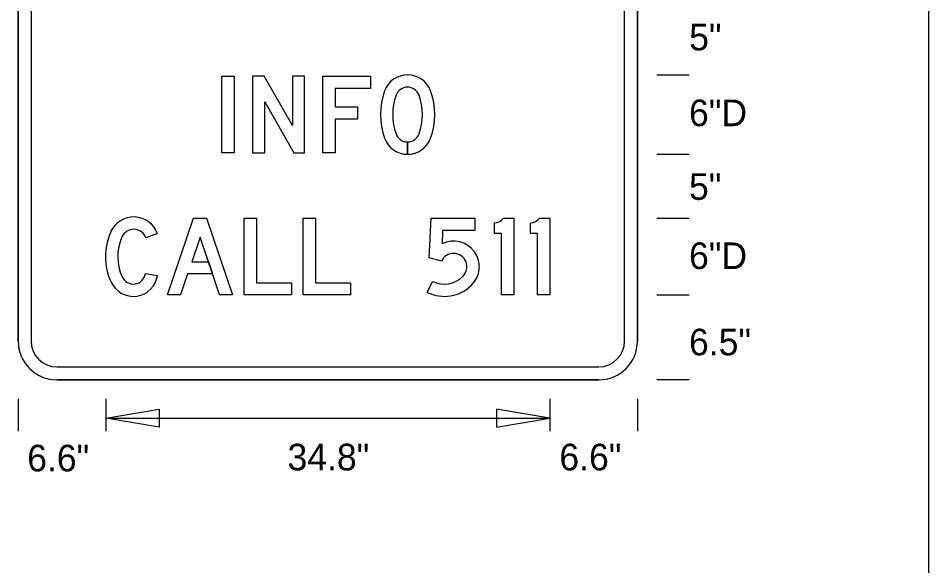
# Model space of a CAD drawing. Extents: x 0 to 770, y 0 to 495.
# Drawn here: x 265.1 to 385, y 345.2 to 417.2 of the extents above; entities that cross this region are included whole.
import ezdxf

# ---------------------------------------------------------------- set-up
doc = ezdxf.new("R2010")
doc.units = 0
for name, color, linetype in [('Default', 7, 'Continuous'), ('Dimension', 7, 'Continuous'), ('GSBWFill', 7, 'Continuous'), ('GSColorFill', 7, 'Continuous'), ('GSDims', 7, 'Continuous'), ('GSOutline', 7, 'Continuous'), ('SheetLines_dp', 7, 'Continuous'), ('TextStructures', 7, 'Continuous')]:
    doc.layers.add(name, color=color, linetype=linetype)

msp = doc.modelspace()

# ---------------------------------------------------------------- linework, layer by layer
at = {"layer": 'Default'}
for p, q in [((265.11, 466.49), (265.11, 374.77)), ((265.11, 374.77), (265.11, 466.49)), ((266.8, 466.49), (266.8, 374.77)), ((344.94, 374.77), (344.94, 466.49)), ((346.64, 374.77), (346.64, 466.49)), ((346.64, 466.49), (346.64, 374.77)), ((270.2, 371.37), (341.54, 371.37)), ((270.2, 369.67), (341.54, 369.67)), ((341.54, 369.67), (270.2, 369.67))]:
    msp.add_line(p, q, dxfattribs=at)
for centre, radius, start, end in [((270.2, 374.77), 5.1, 180, 270), ((270.2, 374.77), 5.1, 180, 270), ((270.2, 374.77), 3.4, 180, 270), ((341.54, 374.77), 5.1, 270, 0), ((341.54, 374.77), 5.1, 270, 0), ((341.54, 374.77), 3.4, 270, 0)]:
    msp.add_arc(centre, radius, start, end, dxfattribs=at)
at = {"layer": 'Dimension'}
for points in [[(276.66, 364.62), (283.67, 365.81), (283.67, 363.43)], [(335.09, 364.62), (328.07, 365.81), (328.07, 363.43)]]:
    msp.add_lwpolyline(points, close=True, dxfattribs=at)
at = {"layer": 'GSBWFill'}
for p, q in [((316.37, 400.95), (316.37, 399.34)), ((316.38, 399.34), (316.38, 400.95)), ((283.45, 388.9), (281.93, 388.35)), ((281.86, 383.64), (283.45, 383.4)), ((318.95, 381.17), (319.66, 382.62)), ((319.66, 382.62), (319.66, 382.62))]:
    msp.add_line(p, q, dxfattribs=at)
for points in [[(291.92, 409.6), (293.53, 409.6), (293.53, 399.51), (291.92, 399.51)], [(302.81, 399.51), (302.81, 409.6), (301.2, 409.6), (301.2, 403.12), (297.49, 409.6), (295.95, 409.6), (295.95, 399.51), (297.57, 399.51), (297.57, 406.22), (301.4, 399.51)], [(311.48, 409.6), (311.48, 407.98), (306.84, 407.98), (306.84, 405.56), (309.78, 405.56), (309.78, 403.95), (306.84, 403.95), (306.84, 399.51), (305.23, 399.51), (305.23, 409.6)], [(284.76, 380.83), (288.19, 390.91), (289.91, 390.91), (293.33, 380.83), (291.63, 380.83), (289.05, 388.42), (287.96, 385.21), (290.14, 385.21), (290.69, 383.6), (287.41, 383.6), (286.47, 380.83)], [(296.46, 382.44), (301.1, 382.44), (301.1, 380.83), (294.85, 380.83), (294.85, 390.91), (296.46, 390.91)], [(304.23, 382.44), (308.87, 382.44), (308.87, 380.83), (302.61, 380.83), (302.61, 390.91), (304.23, 390.91)]]:
    msp.add_lwpolyline(points, close=True, dxfattribs=at)
for points in [[(320.82, 385.27), (319.2, 385.72), (319.46, 390.91), (325.25, 390.91), (325.25, 389.3), (320.99, 389.3), (320.91, 387.55)], [(328.99, 390.91), (330.35, 390.91), (330.35, 380.83), (328.73, 380.83), (328.73, 388.9), (327.83, 388.9), (327.83, 390.3)], [(333.73, 390.91), (335.09, 390.91), (335.09, 380.83), (333.47, 380.83), (333.47, 388.9), (332.57, 388.9), (332.57, 390.3)]]:
    msp.add_lwpolyline(points, dxfattribs=at)
for centre, radius, start, end in [((280.32, 387.76), 3.33, 20.0236, 155.9453), ((327.55, 392.22), 1.94, 278.1148, 317.6823), ((332.29, 392.22), 1.94, 278.1148, 317.6823), ((284.56, 385.87), 7.97, 155.9453, 204.848), ((284.56, 385.87), 6.35, 155.9453, 204.848), ((280.32, 387.76), 1.71, 20.0236, 155.9453), ((322.43, 384.53), 3.38, 314.4153, 116.7914), ((322.43, 384.53), 1.76, 314.4153, 155.5257), ((280.26, 383.88), 3.23, 204.848, 351.506), ((280.26, 383.88), 1.61, 204.848, 351.506), ((321.2, 385.79), 3.53, 244.1304, 314.4153), ((321.2, 385.79), 5.14, 244.1304, 314.4153)]:
    msp.add_arc(centre, radius, start, end, dxfattribs=at)
for centre, major_axis, start_param, end_param in [((316.37, 406.55), (0, 3.23), 5.063177, 7.503193), ((321.82, 404.56), (0, 9.02), 1.220008, 1.921585), ((316.37, 406.55), (0, 1.61), 5.063177, 7.503193), ((310.93, 404.56), (0, 9.02), 4.361601, 5.063177), ((321.82, 404.56), (0, 7.41), 1.220008, 1.921585), ((310.93, 404.56), (0, 7.41), 4.361601, 5.063177), ((316.37, 402.56), (0, 1.61), 1.921585, 3.141593), ((316.37, 402.56), (0, 1.61), 3.141905, 4.361601), ((316.37, 402.56), (0, 3.23), 1.921585, 3.141593), ((316.37, 402.56), (0, 3.23), 3.141749, 4.361601)]:
    msp.add_ellipse(centre, major_axis=major_axis, ratio=0.999993, start_param=start_param, end_param=end_param, dxfattribs=at)
at = {"layer": 'GSColorFill'}
for p, q in [((316.37, 400.95), (316.37, 399.34)), ((316.38, 399.34), (316.38, 400.95)), ((283.45, 388.9), (281.93, 388.35)), ((281.86, 383.64), (283.45, 383.4)), ((318.95, 381.17), (319.66, 382.62)), ((319.66, 382.62), (319.66, 382.62))]:
    msp.add_line(p, q, dxfattribs=at)
for points in [[(291.92, 409.6), (293.53, 409.6), (293.53, 399.51), (291.92, 399.51)], [(302.81, 399.51), (302.81, 409.6), (301.2, 409.6), (301.2, 403.12), (297.49, 409.6), (295.95, 409.6), (295.95, 399.51), (297.57, 399.51), (297.57, 406.22), (301.4, 399.51)], [(311.48, 409.6), (311.48, 407.98), (306.84, 407.98), (306.84, 405.56), (309.78, 405.56), (309.78, 403.95), (306.84, 403.95), (306.84, 399.51), (305.23, 399.51), (305.23, 409.6)], [(284.76, 380.83), (288.19, 390.91), (289.91, 390.91), (293.33, 380.83), (291.63, 380.83), (289.05, 388.42), (287.96, 385.21), (290.14, 385.21), (290.69, 383.6), (287.41, 383.6), (286.47, 380.83)], [(296.46, 382.44), (301.1, 382.44), (301.1, 380.83), (294.85, 380.83), (294.85, 390.91), (296.46, 390.91)], [(304.23, 382.44), (308.87, 382.44), (308.87, 380.83), (302.61, 380.83), (302.61, 390.91), (304.23, 390.91)]]:
    msp.add_lwpolyline(points, close=True, dxfattribs=at)
for points in [[(320.82, 385.27), (319.2, 385.72), (319.46, 390.91), (325.25, 390.91), (325.25, 389.3), (320.99, 389.3), (320.91, 387.55)], [(328.99, 390.91), (330.35, 390.91), (330.35, 380.83), (328.73, 380.83), (328.73, 388.9), (327.83, 388.9), (327.83, 390.3)], [(333.73, 390.91), (335.09, 390.91), (335.09, 380.83), (333.47, 380.83), (333.47, 388.9), (332.57, 388.9), (332.57, 390.3)]]:
    msp.add_lwpolyline(points, dxfattribs=at)
for centre, radius, start, end in [((280.32, 387.76), 3.33, 20.0236, 155.9453), ((327.55, 392.22), 1.94, 278.1148, 317.6823), ((332.29, 392.22), 1.94, 278.1148, 317.6823), ((284.56, 385.87), 7.97, 155.9453, 204.848), ((284.56, 385.87), 6.35, 155.9453, 204.848), ((280.32, 387.76), 1.71, 20.0236, 155.9453), ((322.43, 384.53), 3.38, 314.4153, 116.7914), ((322.43, 384.53), 1.76, 314.4153, 155.5257), ((280.26, 383.88), 3.23, 204.848, 351.506), ((280.26, 383.88), 1.61, 204.848, 351.506), ((321.2, 385.79), 3.53, 244.1304, 314.4153), ((321.2, 385.79), 5.14, 244.1304, 314.4153)]:
    msp.add_arc(centre, radius, start, end, dxfattribs=at)
for centre, major_axis, start_param, end_param in [((316.37, 406.55), (0, 3.23), 5.063177, 7.503193), ((321.82, 404.56), (0, 9.02), 1.220008, 1.921585), ((316.37, 406.55), (0, 1.61), 5.063177, 7.503193), ((310.93, 404.56), (0, 9.02), 4.361601, 5.063177), ((321.82, 404.56), (0, 7.41), 1.220008, 1.921585), ((310.93, 404.56), (0, 7.41), 4.361601, 5.063177), ((316.37, 402.56), (0, 1.61), 1.921585, 3.141593), ((316.37, 402.56), (0, 1.61), 3.141905, 4.361601), ((316.37, 402.56), (0, 3.23), 1.921585, 3.141593), ((316.37, 402.56), (0, 3.23), 3.141749, 4.361601)]:
    msp.add_ellipse(centre, major_axis=major_axis, ratio=0.999993, start_param=start_param, end_param=end_param, dxfattribs=at)
at = {"layer": 'GSDims'}
for p, q in [((349.19, 409.77), (353.43, 409.77)), ((349.19, 409.77), (353.43, 409.77)), ((349.19, 399.34), (353.43, 399.34)), ((349.19, 390.91), (353.43, 390.91)), ((349.19, 380.83), (353.43, 380.83)), ((349.19, 369.71), (353.43, 369.71)), ((265.11, 367.17), (265.11, 362.92)), ((276.66, 367.17), (276.66, 362.92)), ((276.66, 367.17), (276.66, 362.92)), ((335.09, 367.17), (335.09, 362.92)), ((335.09, 367.17), (335.09, 362.92)), ((346.64, 367.17), (346.64, 362.92)), ((276.66, 364.62), (335.09, 364.62))]:
    msp.add_line(p, q, dxfattribs=at)
at = {"layer": 'GSOutline'}
for p, q in [((283.45, 388.9), (281.93, 388.35)), ((281.86, 383.64), (283.45, 383.4)), ((318.95, 381.17), (319.66, 382.62)), ((319.66, 382.62), (319.66, 382.62))]:
    msp.add_line(p, q, dxfattribs=at)
for points in [[(291.92, 409.6), (293.53, 409.6), (293.53, 399.51), (291.92, 399.51)], [(302.81, 399.51), (302.81, 409.6), (301.2, 409.6), (301.2, 403.12), (297.49, 409.6), (295.95, 409.6), (295.95, 399.51), (297.57, 399.51), (297.57, 406.22), (301.4, 399.51)], [(311.48, 409.6), (311.48, 407.98), (306.84, 407.98), (306.84, 405.56), (309.78, 405.56), (309.78, 403.95), (306.84, 403.95), (306.84, 399.51), (305.23, 399.51), (305.23, 409.6)], [(287.41, 383.6), (286.47, 380.83), (284.76, 380.83), (288.19, 390.91), (289.91, 390.91), (293.33, 380.83), (291.63, 380.83), (290.69, 383.6)], [(296.46, 382.44), (301.1, 382.44), (301.1, 380.83), (294.85, 380.83), (294.85, 390.91), (296.46, 390.91)], [(304.23, 382.44), (308.87, 382.44), (308.87, 380.83), (302.61, 380.83), (302.61, 390.91), (304.23, 390.91)], [(287.96, 385.21), (290.14, 385.21), (289.05, 388.42)]]:
    msp.add_lwpolyline(points, close=True, dxfattribs=at)
for points in [[(320.82, 385.27), (319.2, 385.72), (319.46, 390.91), (325.25, 390.91), (325.25, 389.3), (320.99, 389.3), (320.91, 387.55)], [(328.99, 390.91), (330.35, 390.91), (330.35, 380.83), (328.73, 380.83), (328.73, 388.9), (327.83, 388.9), (327.83, 390.3)], [(333.73, 390.91), (335.09, 390.91), (335.09, 380.83), (333.47, 380.83), (333.47, 388.9), (332.57, 388.9), (332.57, 390.3)]]:
    msp.add_lwpolyline(points, dxfattribs=at)
for centre, radius, start, end in [((280.32, 387.76), 3.33, 20.0236, 155.9453), ((327.55, 392.22), 1.94, 278.1148, 317.6823), ((332.29, 392.22), 1.94, 278.1148, 317.6823), ((284.56, 385.87), 7.97, 155.9453, 204.848), ((284.56, 385.87), 6.35, 155.9453, 204.848), ((280.32, 387.76), 1.71, 20.0236, 155.9453), ((322.43, 384.53), 3.38, 314.4153, 116.7914), ((322.43, 384.53), 1.76, 314.4153, 155.5257), ((280.26, 383.88), 3.23, 204.848, 351.506), ((280.26, 383.88), 1.61, 204.848, 351.506), ((321.2, 385.79), 3.53, 244.1304, 314.4153), ((321.2, 385.79), 5.14, 244.1304, 314.4153)]:
    msp.add_arc(centre, radius, start, end, dxfattribs=at)
for centre, major_axis, start_param, end_param in [((316.37, 406.55), (0, 3.23), 5.063177, 7.503193), ((321.82, 404.56), (0, 9.02), 1.220008, 1.921585), ((316.37, 406.55), (0, 1.61), 5.063177, 7.503193), ((310.93, 404.56), (0, 9.02), 4.361601, 5.063177), ((321.82, 404.56), (0, 7.41), 1.220008, 1.921585), ((310.93, 404.56), (0, 7.41), 4.361601, 5.063177), ((316.37, 402.56), (0, 1.61), 1.921585, 4.361601), ((316.37, 402.56), (0, 3.23), 1.921585, 4.361601)]:
    msp.add_ellipse(centre, major_axis=major_axis, ratio=0.999993, start_param=start_param, end_param=end_param, dxfattribs=at)
at = {"layer": 'SheetLines_dp'}
msp.add_line((385, 0), (385, 495), dxfattribs=at)

# ---------------------------------------------------------------- texts
at = {"layer": 'TextStructures'}
for s, p in [('5"', (353.45, 413)), ('6"D', (353.43, 403.03)), ('5"', (353.43, 393.34)), ('6"D', (353.43, 384.24)), ('6.5"', (353.43, 372.89)), ('6.6"', (266.29, 357.63)), ('34.8"', (300.56, 357.76)), ('6.6"', (336.36, 357.76))]:
    msp.add_text(s, height=3.5, dxfattribs=at).set_placement(p)

doc.saveas('drawing.dxf')
